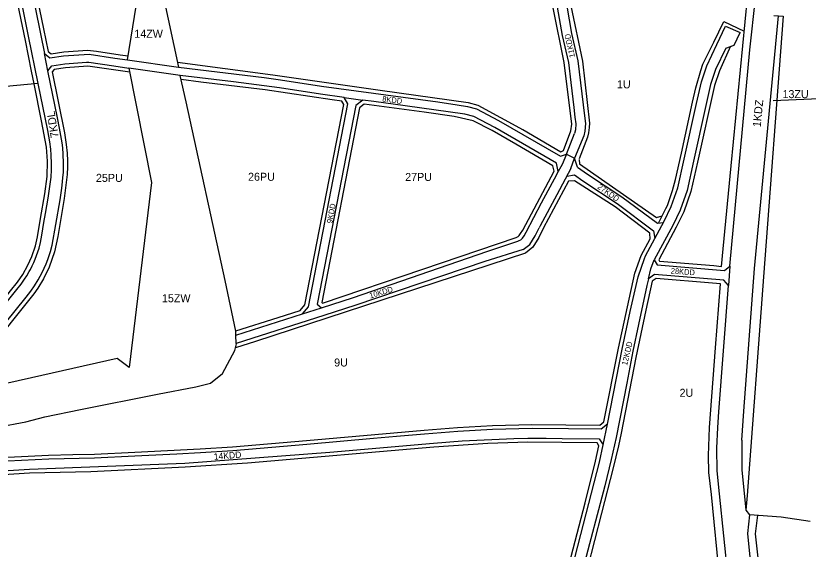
# Model space of a CAD drawing. Extents: x 7428203 to 7432868, y 5542672 to 5545406.
# Drawn here: x 7430430 to 7431420, y 5543859 to 5544524 of the extents above; entities that cross this region are included whole.
import ezdxf

# ---------------------------------------------------------------- set-up
doc = ezdxf.new("R2010")
doc.units = 0
for name, color, linetype in [('_GRANICA_MIASTA', 7, 'Continuous'), ('granicaBulwary', 7, 'Continuous'), ('MPZP_uchwalone_nieobowiazujace jeszcze_SZRAF', 7, 'Continuous')]:
    doc.layers.add(name, color=color, linetype=linetype)

msp = doc.modelspace()

# ---------------------------------------------------------------- linework, layer by layer
at = {"layer": '_GRANICA_MIASTA'}
for p, q in [((7430604.98, 5544592.38), (7430633.38, 5544460.3)), ((7431346.8, 5544481.9), (7431353.84, 5544546.3)), ((7431388.4, 5544523.8), (7431364.07, 5544198.77)), ((7431376.85, 5544524.65), (7431388.4, 5544523.8)), ((7431305.61, 5544488.59), (7431316.53, 5544511.55)), ((7431316.53, 5544511.55), (7431334.86, 5544503.54)), ((7431327.38, 5544487.8), (7431334.86, 5544503.54)), ((7431292.99, 5544462.02), (7431305.61, 5544488.59)), ((7431316.72, 5544484.01), (7431304.14, 5544457.54)), ((7431316.72, 5544484.01), (7431327.38, 5544487.8)), ((7431321.92, 5544211.85), (7431346.8, 5544481.9)), ((7430635.44, 5544449.92), (7430571.27, 5544459.14)), ((7430571.27, 5544459.14), (7430599.39, 5544316.2)), ((7431286.32, 5544441.98), (7431292.99, 5544462.02)), ((7431304.14, 5544457.54), (7431297.89, 5544438.74)), ((7430642.68, 5544416.89), (7430635.44, 5544449.92)), ((7431280.12, 5544415.08), (7431286.32, 5544441.98)), ((7431297.89, 5544438.74), (7431291.83, 5544412.46)), ((7430691.42, 5544193.97), (7430642.68, 5544416.89)), ((7430840.14, 5544422.46), (7430863.59, 5544419.22)), ((7431264.97, 5544345.58), (7431280.12, 5544415.08)), ((7431291.83, 5544412.46), (7431276.68, 5544342.95)), ((7431117.86, 5544351.65), (7431127.83, 5544377.61)), ((7431139.48, 5544374.73), (7431127.74, 5544346.69)), ((7431117.86, 5544351.65), (7431127.74, 5544346.69)), ((7431123.16, 5544333.64), (7431127.74, 5544346.69)), ((7431131.44, 5544335.49), (7431127.74, 5544346.69)), ((7431256.96, 5544309.86), (7431264.97, 5544345.58)), ((7431276.68, 5544342.95), (7431268.51, 5544306.54)), ((7431123.16, 5544333.64), (7431105.78, 5544301.14)), ((7431118.1, 5544324.18), (7431127.79, 5544325.85)), ((7430599.39, 5544316.2), (7430571.63, 5544085.3)), ((7431248.71, 5544286.44), (7431256.96, 5544309.86)), ((7431268.51, 5544306.54), (7431259.81, 5544281.82)), ((7431105.78, 5544301.14), (7431084.94, 5544262.17)), ((7431239.85, 5544268.13), (7431248.71, 5544286.44)), ((7431259.81, 5544281.82), (7431250.54, 5544262.67)), ((7431216.47, 5544224.65), (7431239.85, 5544268.13)), ((7431231.49, 5544265.75), (7431238.91, 5544266.38)), ((7431084.94, 5544262.17), (7431083.75, 5544259.73)), ((7431226.58, 5544256.09), (7431228.16, 5544246.39)), ((7431250.54, 5544262.67), (7431227.46, 5544219.73)), ((7431063.91, 5544232.54), (7431015.88, 5544217.76)), ((7431015.88, 5544217.76), (7430854.88, 5544163.28)), ((7431207.33, 5544198.74), (7431215.19, 5544221.63)), ((7431215.19, 5544221.63), (7431216.47, 5544224.65)), ((7431227.46, 5544219.73), (7431231.25, 5544213.4)), ((7431231.25, 5544213.4), (7431315.39, 5544206.37)), ((7431315.39, 5544206.37), (7431321.92, 5544211.85)), ((7431321.92, 5544211.85), (7431320.03, 5544187.92)), ((7431197.34, 5544155.42), (7431207.33, 5544198.74)), ((7431220.21, 5544196.26), (7431218.27, 5544187.95)), ((7431227.87, 5544201.64), (7431220.21, 5544196.26)), ((7431314.5, 5544194.41), (7431227.87, 5544201.64)), ((7431364.07, 5544198.77), (7431343.44, 5543925.8)), ((7430704.81, 5544130.56), (7430691.42, 5544193.97)), ((7431218.27, 5544187.95), (7431207.89, 5544139.2)), ((7431308.16, 5544030.14), (7431320.03, 5544187.92)), ((7431320.03, 5544187.92), (7431314.5, 5544194.41)), ((7430787.97, 5544152.39), (7430811.85, 5544160.02)), ((7430854.88, 5544163.28), (7430814.89, 5544150.5)), ((7430814.89, 5544150.5), (7430705.48, 5544115.51)), ((7431187.53, 5544108.38), (7431197.34, 5544155.42)), ((7431207.89, 5544139.2), (7431200.76, 5544105.73)), ((7430705.02, 5544125.87), (7430704.81, 5544130.56)), ((7430705.48, 5544115.51), (7430705.02, 5544125.87)), ((7430688.24, 5544078.05), (7430703.65, 5544106.55)), ((7430703.65, 5544106.55), (7430705.51, 5544114.87)), ((7430705.51, 5544114.87), (7430705.48, 5544115.51)), ((7431169.21, 5544014.62), (7431187.53, 5544108.38)), ((7430556.6, 5544096.8), (7430351.39, 5544050.23)), ((7430571.63, 5544085.3), (7430556.6, 5544096.8)), ((7431200.76, 5544105.73), (7431193.28, 5544065.85)), ((7430673.38, 5544065.63), (7430688.24, 5544078.05)), ((7430607.17, 5544051.99), (7430654.86, 5544061.19)), ((7430654.86, 5544061.19), (7430673.38, 5544065.63)), ((7431193.28, 5544065.85), (7431179.84, 5543998.02)), ((7430510.83, 5544032.94), (7430607.17, 5544051.99)), ((7430466.5, 5544023.7), (7430510.83, 5544032.94)), ((7431306.69, 5544010.57), (7431308.16, 5544030.14)), ((7431336.87, 5543994.72), (7431339.31, 5544031)), ((7430376.69, 5544005.34), (7430442.42, 5544017.56)), ((7430442.42, 5544017.56), (7430466.5, 5544023.7)), ((7431025.49, 5544007.96), (7430982.03, 5544005.63)), ((7431074.8, 5544009.15), (7431025.49, 5544007.96)), ((7431120.26, 5544008.69), (7431074.8, 5544009.15)), ((7431161.3, 5544008.34), (7431120.26, 5544008.69)), ((7431169.21, 5544014.62), (7431161.3, 5544008.34)), ((7431163.66, 5543988.83), (7431169.21, 5544014.62)), ((7430905.41, 5543999.22), (7430876.98, 5543996.76)), ((7430940.49, 5544002.16), (7430905.41, 5543999.22)), ((7430982.03, 5544005.63), (7430940.49, 5544002.16)), ((7431179.84, 5543998.02), (7431173.73, 5543970.49)), ((7430793.67, 5543989.27), (7430735.33, 5543984.35)), ((7430876.98, 5543996.76), (7430793.67, 5543989.27)), ((7430822.44, 5543979.62), (7430951.57, 5543991.04)), ((7430951.57, 5543991.04), (7430987.68, 5543993.92)), ((7430987.68, 5543993.92), (7431052.25, 5543996.61)), ((7431052.25, 5543996.61), (7431069.66, 5543997.03)), ((7431069.66, 5543997.03), (7431092.3, 5543996.97)), ((7431092.3, 5543996.97), (7431112.27, 5543996.77)), ((7431112.27, 5543996.77), (7431158.71, 5543996.18)), ((7431158.71, 5543996.18), (7431163.66, 5543988.83)), ((7430660.59, 5543978.99), (7430631.1, 5543977.3)), ((7430641.3, 5543965.87), (7430822.44, 5543979.62)), ((7430700.98, 5543981.37), (7430660.59, 5543978.99)), ((7430735.33, 5543984.35), (7430700.98, 5543981.37)), ((7430471.2, 5543970.94), (7430420.25, 5543968.49)), ((7430528.46, 5543972.27), (7430471.2, 5543970.94)), ((7430578.76, 5543974.63), (7430528.46, 5543972.27)), ((7430631.1, 5543977.3), (7430578.76, 5543974.63)), ((7431173.73, 5543970.49), (7431165.55, 5543937.59)), ((7430360.29, 5543952.75), (7430447, 5543958.42)), ((7430447, 5543958.42), (7430641.3, 5543965.87)), ((7431165.55, 5543937.59), (7431123.36, 5543776.97)), ((7431343.44, 5543925.8), (7431342.05, 5543907.45)), ((7431386.19, 5543898.41), (7431346.33, 5543901.64)), ((7431422.33, 5543893.08), (7431386.19, 5543898.41))]:
    msp.add_line(p, q, dxfattribs=at)
for points in [[(7430457.97, 5544439.94), (7430446.05, 5544498.9), (7430427.95, 5544588.48), (7430420.35, 5544625.11)], [(7430470.09, 5544455.7), (7430465.74, 5544477.21), (7430472.67, 5544471.8), (7430489.65, 5544474.52), (7430521.79, 5544476.48), (7430553.88, 5544471.74), (7430569.42, 5544469.51), (7430584.87, 5544565.16), (7430563.07, 5544584.92), (7430554.24, 5544583.75), (7430532.74, 5544581.22), (7430519.71, 5544580.53), (7430493.95, 5544579.21), (7430453.82, 5544577.48), (7430447.41, 5544567.9), (7430460.75, 5544501.87), (7430465.74, 5544477.21)], [(7431105.3, 5544561.03), (7431106.35, 5544535.11), (7431112.57, 5544499.95), (7431120.29, 5544466.13), (7431123.22, 5544441.19), (7431126.91, 5544409.92), (7431128.31, 5544398.07), (7431129.4, 5544389.65), (7431128.94, 5544382.08), (7431127.83, 5544377.61)], [(7431117.44, 5544557.87), (7431118.31, 5544536.4), (7431124.33, 5544502.33), (7431132.13, 5544468.17), (7431140.22, 5544399.55), (7431141.45, 5544390.06), (7431140.85, 5544380.26), (7431139.48, 5544374.73)], [(7431339.31, 5544031), (7431352.78, 5544209), (7431382.53, 5544524.23)], [(7430417.17, 5544141.27), (7430442.92, 5544173.26), (7430448.83, 5544180.6), (7430453.44, 5544187.22), (7430458.17, 5544194.87), (7430463.17, 5544204.14), (7430468.02, 5544214.93), (7430470.1, 5544220.23), (7430473.42, 5544230.29), (7430475.46, 5544238.15), (7430480.04, 5544263.9), (7430485.31, 5544294.55), (7430487.59, 5544309.3), (7430488.1, 5544313.04), (7430489, 5544321.97), (7430489.45, 5544329.17), (7430489.61, 5544335.11), (7430489.63, 5544340.5), (7430489.24, 5544351.51), (7430488.61, 5544359.44), (7430487.81, 5544365.89), (7430484.66, 5544384.16), (7430481.93, 5544397.12), (7430470.09, 5544455.7), (7430475.05, 5544462.06), (7430491.42, 5544464.62), (7430518.2, 5544466.48), (7430521.12, 5544466.48), (7430552.43, 5544461.85), (7430571.27, 5544459.14)], [(7430569.42, 5544469.51), (7430633.38, 5544460.3), (7430740.24, 5544447.34), (7430760.86, 5544444.53), (7430811.92, 5544436.53), (7430957.31, 5544416.86), (7430981.37, 5544413.37), (7430994.17, 5544411.27), (7431005.45, 5544408.24), (7431033.05, 5544393.91), (7431110.24, 5544349.14), (7431117.86, 5544351.65), (7431112.34, 5544338.85), (7431107.55, 5544329.89), (7431105.22, 5544340.49), (7431028.24, 5544385.14), (7431002.04, 5544398.75), (7430990.73, 5544401.69), (7430916.34, 5544412.18), (7430877.04, 5544417.36), (7430863.59, 5544419.22), (7430854.75, 5544412.37), (7430806.64, 5544164.65), (7430811.85, 5544160.02), (7430851.76, 5544172.78), (7431018.42, 5544230.14), (7431057, 5544242.92), (7431058.82, 5544243.72), (7431060.71, 5544244.78), (7431062.82, 5544246.81), (7431064.84, 5544249.88), (7431067.61, 5544254.32), (7431086.71, 5544290.93), (7431105.7, 5544326.44), (7431107.55, 5544329.89)], [(7430705.02, 5544125.87), (7430787.97, 5544152.39), (7430795.78, 5544161.19), (7430844.9, 5544414.72), (7430840.14, 5544422.46), (7430810.43, 5544426.64), (7430759.42, 5544434.64), (7430702.11, 5544441.87), (7430635.44, 5544449.92)], [(7430384.94, 5544125.16), (7430431.24, 5544182.66), (7430436.82, 5544189.6), (7430440.93, 5544195.5), (7430443.69, 5544199.89), (7430446.9, 5544205.38), (7430448.26, 5544207.93), (7430450.4, 5544212.15), (7430452.42, 5544216.56), (7430454.14, 5544220.61), (7430455.99, 5544225.32), (7430459.03, 5544234.53), (7430460.84, 5544241.52), (7430462.71, 5544250.78), (7430465.24, 5544266.38), (7430467.2, 5544277.74), (7430470.5, 5544296.91), (7430472.75, 5544311.46), (7430474.05, 5544323.19), (7430474.54, 5544332.24), (7430474.63, 5544340.19), (7430474.27, 5544350.65), (7430473.69, 5544357.92), (7430472.56, 5544367.02), (7430469.94, 5544381.26), (7430457.97, 5544439.94), (7430248.78, 5544420.45)], [(7431131.44, 5544335.49), (7431144, 5544326.77), (7431187.05, 5544298.43), (7431231.49, 5544265.75)], [(7431127.79, 5544325.85), (7431138.4, 5544318.48), (7431181.34, 5544290.23), (7431226.58, 5544256.09)], [(7431063.91, 5544232.54), (7431072.1, 5544239.08), (7431078.85, 5544249.93), (7431083.75, 5544259.73)], [(7431220.21, 5544196.26), (7431223.1, 5544208.59), (7431227.46, 5544219.73)], [(7431309.1, 5543927.71), (7431306.2, 5543956.49), (7431305.78, 5543984.85), (7431306.69, 5544010.57)], [(7431094.31, 5543717.17), (7431101.48, 5543744.76), (7431145.8, 5543915.56), (7431159, 5543967.17), (7431163.66, 5543988.83)], [(7431336.87, 5543994.72), (7431337.06, 5543957.82), (7431342.05, 5543907.45), (7431346.33, 5543901.64), (7431344.13, 5543878.23), (7431348.52, 5543831.97), (7431390, 5543702.36), (7431390.73, 5543691.85), (7431392.19, 5543663.75), (7431392.48, 5543658.26), (7431391.71, 5543646.79), (7431385.31, 5543618.42), (7431364, 5543513.86)], [(7431333.87, 5543519.93), (7431356.3, 5543627.18), (7431361.52, 5543652.65), (7431362.19, 5543670.59), (7431359.03, 5543701.57), (7431327.35, 5543799.07), (7431319.67, 5543822.68), (7431309.1, 5543927.71)]]:
    msp.add_lwpolyline(points, dxfattribs=at)
at = {"layer": 'granicaBulwary'}
msp.add_line((7431443.25, 5544421.06), (7431376.15, 5544418.34), dxfattribs=at)
at = {"layer": 'MPZP_uchwalone_nieobowiazujace jeszcze_SZRAF'}
for p, q in [((7431301.82, 5544491.41), (7431314.42, 5544517.15)), ((7431314.42, 5544517.15), (7431339.84, 5544505.41)), ((7431288.34, 5544463.89), (7431301.82, 5544491.41)), ((7431322.86, 5544486.63), (7431308.79, 5544455.67)), ((7431285.73, 5544456.04), (7431288.34, 5544463.89)), ((7431279.46, 5544434.49), (7431285.73, 5544456.04)), ((7431308.79, 5544455.67), (7431302.7, 5544437.38)), ((7431275.38, 5544416.79), (7431279.46, 5544434.49)), ((7431302.7, 5544437.38), (7431281.56, 5544341.86)), ((7431261.42, 5544352.78), (7431275.38, 5544416.79)), ((7431254.17, 5544320.27), (7431261.42, 5544352.78)), ((7431281.56, 5544341.86), (7431273.33, 5544305.16)), ((7431120.46, 5544318), (7431089.35, 5544259.81)), ((7431250.39, 5544306.26), (7431254.17, 5544320.27)), ((7431245.59, 5544292.62), (7431250.39, 5544306.26)), ((7431273.33, 5544305.16), (7431264.43, 5544279.89)), ((7431241.97, 5544283.99), (7431243.41, 5544286.96)), ((7431243.41, 5544286.96), (7431244.24, 5544288.79)), ((7431244.24, 5544288.79), (7431245.59, 5544292.62)), ((7431232.7, 5544265.61), (7431240.37, 5544280.68)), ((7431240.37, 5544280.68), (7431241.97, 5544283.99)), ((7431264.43, 5544279.89), (7431254.99, 5544260.4)), ((7431254.99, 5544260.4), (7431233.2, 5544219.87)), ((7431211.29, 5544225.22), (7431222.42, 5544245.99)), ((7431066.55, 5544227.91), (7430729.33, 5544117.89)), ((7431203.16, 5544203.14), (7431211.29, 5544225.22)), ((7431233.2, 5544219.87), (7431234.22, 5544218.17)), ((7431234.22, 5544218.17), (7431301.89, 5544212.52)), ((7431182.62, 5544109.36), (7431203.16, 5544203.14)), ((7431229.98, 5544196.44), (7431224.69, 5544193.29)), ((7431300.19, 5544190.78), (7431229.98, 5544196.44)), ((7431224.69, 5544193.29), (7431216.82, 5544157.13)), ((7431216.82, 5544157.13), (7431204.35, 5544097.72)), ((7430729.33, 5544117.89), (7430704.41, 5544109.95)), ((7431164.7, 5544017.42), (7431182.62, 5544109.36)), ((7431204.35, 5544097.72), (7431186.02, 5544003.48)), ((7431159.57, 5544013.36), (7431164.7, 5544017.42)), ((7430793.23, 5543994.25), (7430940.07, 5544007.14)), ((7430940.07, 5544007.14), (7430981.69, 5544010.62)), ((7430981.69, 5544010.62), (7431025.3, 5544012.96)), ((7431025.3, 5544012.96), (7431074.76, 5544014.15)), ((7431074.76, 5544014.15), (7431159.57, 5544013.36)), ((7431186.02, 5544003.48), (7431182.85, 5543987.44)), ((7430700.62, 5543986.36), (7430793.23, 5543994.25)), ((7431182.85, 5543987.44), (7431176.27, 5543959.98)), ((7430528.31, 5543977.27), (7430578.52, 5543979.63)), ((7430578.52, 5543979.63), (7430660.3, 5543983.98)), ((7430660.3, 5543983.98), (7430700.62, 5543986.36)), ((7430419.97, 5543973.48), (7430471, 5543975.94)), ((7430471, 5543975.94), (7430501.45, 5543976.84)), ((7430501.45, 5543976.84), (7430528.31, 5543977.27)), ((7431176.27, 5543959.98), (7431161.79, 5543903.59)), ((7431161.79, 5543903.59), (7431133.34, 5543795.27))]:
    msp.add_line(p, q, dxfattribs=at)
for points in [[(7430452.96, 5544439.48), (7430449.8, 5544455.13), (7430442.03, 5544493.58), (7430434.78, 5544529.46), (7430415.09, 5544626.01)], [(7430567.92, 5544580.53), (7430542.08, 5544577.28), (7430529.17, 5544576.02), (7430511.85, 5544575.12), (7430456.57, 5544572.6), (7430452.66, 5544566.75), (7430464.55, 5544508.32), (7430470.27, 5544480.01), (7430474.03, 5544477.08), (7430489.96, 5544479.56), (7430519.47, 5544481.48), (7430530.94, 5544480.24), (7430560.29, 5544475.87), (7430570.21, 5544474.44)], [(7431063.14, 5544382.37), (7431110.81, 5544354.59), (7431113.93, 5544356.36), (7431123.48, 5544380.83), (7431124.35, 5544388.98), (7431114.91, 5544466.23), (7431101.37, 5544534.57), (7431100.3, 5544560.99), (7431097.8, 5544563.11)], [(7431180.04, 5544548.5), (7431162.91, 5544549.87), (7431126.42, 5544557.33), (7431122.79, 5544555.58), (7431123.29, 5544536.94), (7431137.91, 5544467.8), (7431146.47, 5544390.23), (7431146.14, 5544384.86), (7431145.52, 5544378.33), (7431144.09, 5544372.8), (7431133.54, 5544345.78)], [(7431301.89, 5544212.52), (7431311.45, 5544211.59), (7431313.56, 5544233.49), (7431323.58, 5544337.28), (7431343.89, 5544547.26), (7431333.82, 5544547.21)], [(7430632.12, 5544466.45), (7430751.23, 5544450.89), (7430885.33, 5544431.64), (7430995.22, 5544416.16), (7431007.27, 5544412.93), (7431063.68, 5544381.92)], [(7430520.1, 5544461.48), (7430491.98, 5544459.65), (7430477.78, 5544457.43), (7430475.44, 5544454.44), (7430490.83, 5544378.22), (7430493.13, 5544363.66), (7430494.14, 5544353.06), (7430494.53, 5544343.5), (7430494.61, 5544335.77), (7430494.27, 5544326.12), (7430490.61, 5544296.21), (7430482.65, 5544248.81), (7430478.48, 5544229.89), (7430471.7, 5544210.79), (7430464.65, 5544196.18), (7430457.58, 5544184.42), (7430452.55, 5544177.25), (7430392.7, 5544102.9), (7430377.35, 5544083.83), (7430368.08, 5544072.13), (7430362.82, 5544063.77), (7430359.23, 5544056.71), (7430357.03, 5544051.51)], [(7430572.29, 5544453.94), (7430528.96, 5544460.32), (7430520.1, 5544461.48)], [(7430704.72, 5544131.02), (7430757.56, 5544147.92), (7430785.14, 5544156.73), (7430791.13, 5544163.48), (7430839.62, 5544413.76), (7430837.12, 5544417.83), (7430825.21, 5544419.51), (7430741.33, 5544432.05), (7430661.14, 5544441.78), (7430636.57, 5544444.75)], [(7430329.27, 5544045.04), (7430332.97, 5544058.17), (7430337.6, 5544069.56), (7430342.97, 5544079.41), (7430351.44, 5544091.54), (7430371.01, 5544115.81), (7430404.6, 5544157.55), (7430423.43, 5544180.94), (7430432.3, 5544191.95), (7430438.74, 5544201.41), (7430445.23, 5544212.97), (7430450.01, 5544223.76), (7430454.54, 5544237.14), (7430457.12, 5544248.36), (7430461.06, 5544271.56), (7430466.22, 5544302.18), (7430469.07, 5544323.69), (7430469.53, 5544343.01), (7430468.34, 5544360.41), (7430462.3, 5544393.27), (7430452.96, 5544439.48)], [(7431133.57, 5544344.91), (7431134.3, 5544339.6), (7431230.4, 5544272.69), (7431237.42, 5544274.88)], [(7431222.24, 5544245.67), (7431221.94, 5544253.01), (7431178.46, 5544286.14), (7431127.94, 5544318.48), (7431120.46, 5544318)], [(7431089.35, 5544259.81), (7431083.22, 5544247.49), (7431075.89, 5544235.71), (7431066.55, 5544227.91)], [(7431349.2, 5543689.58), (7431349.15, 5543699.08), (7431349.15, 5543699.08), (7431328.95, 5543762.85), (7431309.36, 5543820.12), (7431299.15, 5543926.71), (7431295.65, 5543954.49), (7431295.22, 5543975.54), (7431296.68, 5544010.53), (7431304.12, 5544109.78), (7431310.11, 5544189.63), (7431300.19, 5544190.78)], [(7431096.64, 5543746.01), (7431141.07, 5543916.56), (7431154.13, 5543968.32), (7431158.32, 5543987.8), (7431156.03, 5543991.21), (7431112.21, 5543991.77), (7431069.72, 5543992.03), (7431019.7, 5543990.63), (7430951.97, 5543986.06), (7430719.62, 5543965.92), (7430641.58, 5543960.87), (7430523.7, 5543955.12), (7430447.22, 5543953.43), (7430362.74, 5543947.9), (7430360.14, 5543944.81), (7430364.22, 5543909.88), (7430366.87, 5543843.51)], [(7431356.33, 5543901.17), (7431353.52, 5543877.68), (7431358.38, 5543832.7), (7431379.41, 5543768.24), (7431399.89, 5543704.26), (7431401.46, 5543671.4)]]:
    msp.add_lwpolyline(points, dxfattribs=at)
msp.add_lwpolyline([(7430864.99, 5544413.98), (7430859.3, 5544409.57), (7430812.09, 5544166.5), (7430813.04, 5544165.65), (7430938.54, 5544208.12), (7431055.21, 5544247.59), (7431057.7, 5544248.83), (7431058.95, 5544250.02), (7431060.63, 5544252.58), (7431063.27, 5544256.81), (7431102.27, 5544330.62), (7431100.81, 5544337.27), (7431054.52, 5544364.12), (7431025.16, 5544381.11), (7431001.35, 5544393.47), (7430977.39, 5544398.79), (7430939.91, 5544404.03)], close=True, dxfattribs=at)

# ---------------------------------------------------------------- texts
at = {"layer": 'granicaBulwary'}
for s, p in [('14ZW', (7430578.06, 5544497)), ('1U', (7431180.94, 5544433.86)), ('13ZU', (7431387.69, 5544421.67)), ('25PU', (7430530.17, 5544317.1)), ('26PU', (7430720.13, 5544318.48)), ('27PU', (7430916.4, 5544318.24)), ('15ZW', (7430612.58, 5544166.85)), ('9U', (7430827.66, 5544086.66)), ('2U', (7431259.12, 5544048.81))]:
    msp.add_text(s, height=10, dxfattribs=at).set_placement(p)
for s, height, rotation, p in [('11KDD', 7, 101.99758, (7431128.61, 5544472.99)), ('8KDD', 7, 353.10638, (7430887.45, 5544417.41)), ('1KDZ', 10, 84.37885, (7431360.39, 5544385.09)), ('7KDL', 10, 99.19923, (7430483.75, 5544372.9)), ('27KDD', 7, 325.21422, (7431155.91, 5544309.29)), ('9KDD', 7, 79.41478, (7430825.18, 5544264.92)), ('28KDD', 7, 355.69803, (7431247.89, 5544202.64)), ('10KDD', 7, 16.92074, (7430872.88, 5544171.48)), ('12KDD', 7, 76.81053, (7431193.54, 5544087.58)), ('14KDD', 8, 4.35539, (7430677.62, 5543970.15))]:
    msp.add_text(s, height=height, rotation=rotation, dxfattribs=at).set_placement(p)

doc.saveas('drawing.dxf')
